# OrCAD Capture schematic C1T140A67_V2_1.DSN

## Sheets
1 002_Log: title: Telink-Semi; rev: V2.1; note: C1T140A67
2 001_chip: size A4
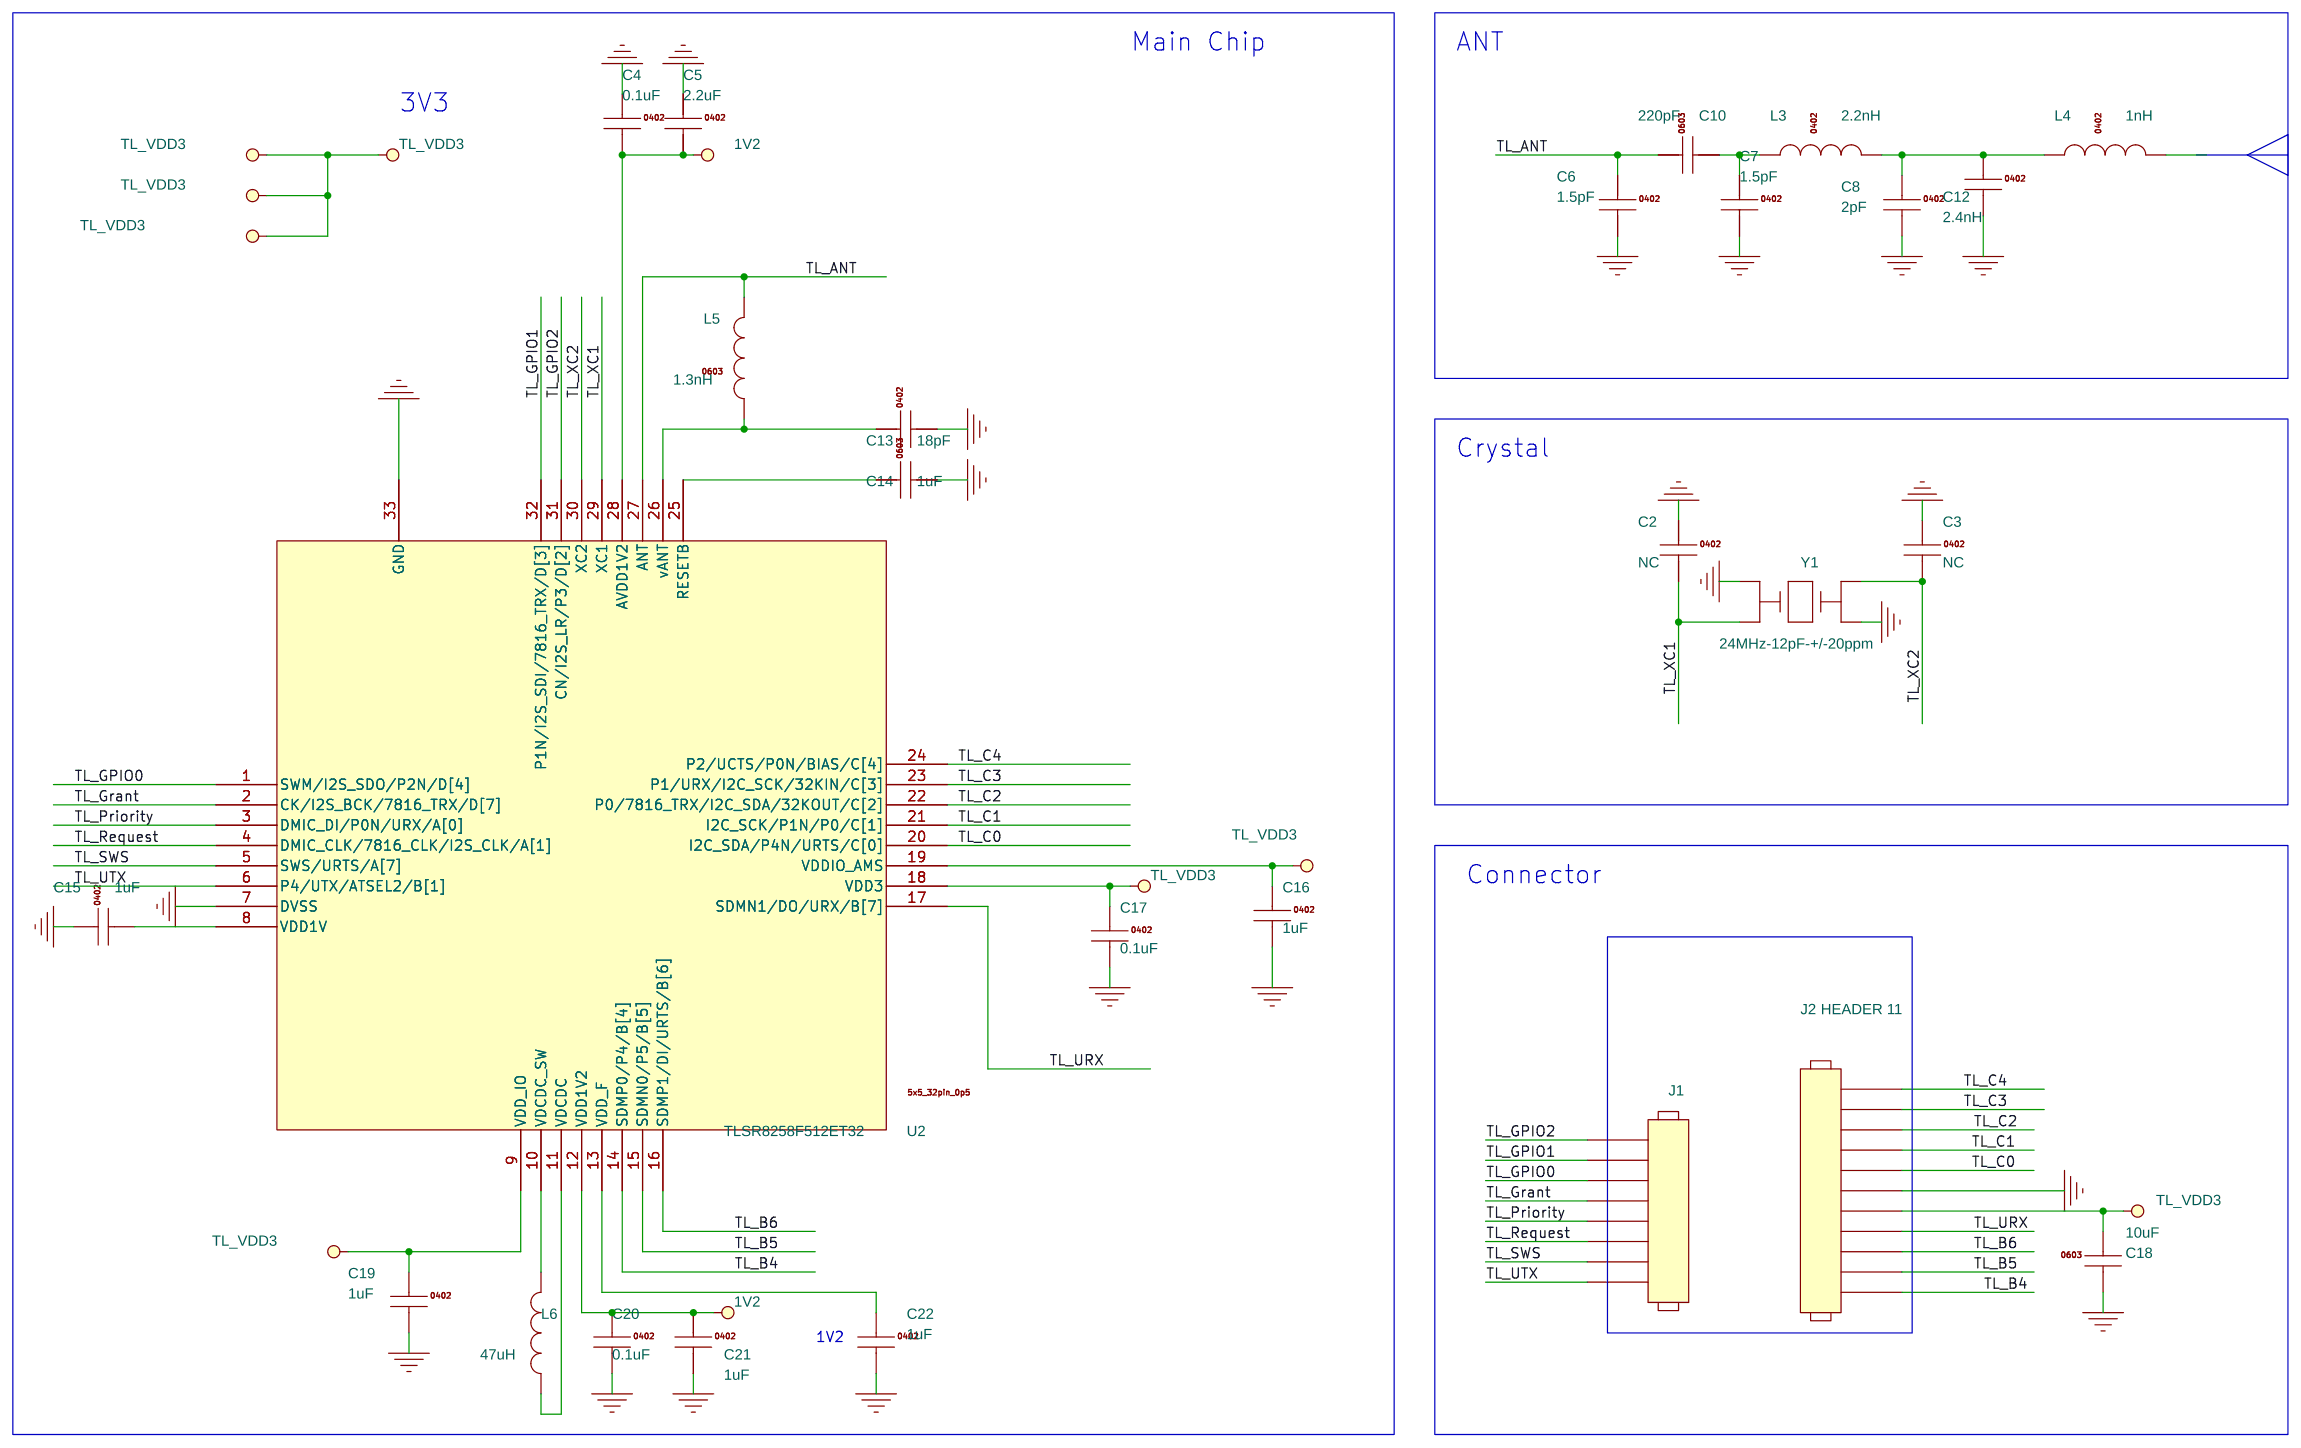
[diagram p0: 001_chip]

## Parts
C2  NC  [0201]
C3  NC  [0201]
C4  0.1uF  [0201]
C5  2.2uF  [0201]
C6  1.5pF  [0201]
C7  1.5pF  [0201]
C8  2pF  [0201]
C10  220pF  [0201]
C12  2.4nH  [0201]
C13  18pF  [0201]
C14  1uF  [0201]
C15  1uF  [0201]
C16  1uF  [0201]
C17  0.1uF  [0201]
C18  10uF  [0402]
C19  1uF  [0201]
C20  0.1uF  [0201]
C21  1uF  [0201]
C22  1uF  [0201]
J1  HEADER 8  [hdr_1p5_1x8]
J2  HEADER 11  [hdr_1p5_1x11]
L3  2.2nH  [0201]
L4  1nH  [0201]
L5  1.3nH  [0201]
L6  47uH  [0805L]
U2  TLSR8258F512ET32  [qfn_5x5_32pin_0p5_2p50x2p50]
Y1  24MHz-12pF-+/-20ppm  [osccc200x250x080]

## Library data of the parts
C2 C3 = C1005_NC
C4 C5 C16 C17 C19-C22 = C1005X5R1C104K
C6-C8 C12 = C1005C0G1H020C
C10 = C1608_NC
C13 = C1005C0G1H100D
C14 = C1608X5R1C105M
C15 = C1005X5R1C105K
C18 = C1608X5R0J106M
J1 = HEADER_8
J2 = HEADER_11
L3 L4 = MLK1005S3N3ST
L5 = MLK1608_000R
L6 = IND_0
U2 = TLSR8258F512ET32
Y1 = CRYSTAL4_SM_0

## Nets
1V2: C4.2 C5.2 C20.1 C21.1 U2.12(VDD1V2) U2.28(AVDD1V2)
GND: C2.1 C3.1 C4.1 C5.1 C6.2 C7.2 C8.2 C12.2 C13.2 C14.2 C15.1 C16.2 C17.2 C18.2 C19.2 C20.2 C21.2 C22.2 J2.6 U2.7(DVSS) U2.33(GND) Y1.2 Y1.4
TL_ANT: C6.1 C10.1 L5.2 U2.27(ANT)
TL_B4: J2.11 U2.14(SDMP0/P4/B[4])
TL_B5: J2.10 U2.15(SDMN0/P5/B[5])
TL_B6: J2.9 U2.16(SDMP1/DI/URTS/B[6])
TL_C0: J2.5 U2.20(I2C_SDA/P4N/URTS/C[0])
TL_C1: J2.4 U2.21(I2C_SCK/P1N/P0/C[1])
TL_C2: J2.3 U2.22(P0/7816_TRX/I2C_SDA/32KOUT/C[2])
TL_C3: J2.2 U2.23(P1/URX/I2C_SCK/32KIN/C[3])
TL_C4: J2.1 U2.24(P2/UCTS/P0N/BIAS/C[4])
TL_GPIO0: J1.3 U2.1(SWM/I2S_SDO/P2N/D[4])
TL_GPIO1: J1.2 U2.32(P1N/I2S_SDI/7816_TRX/D[3])
TL_GPIO2: J1.1 U2.31(CN/I2S_LR/P3/D[2])
TL_Grant: J1.4 U2.2(CK/I2S_BCK/7816_TRX/D[7])
TL_Priority: J1.5 U2.3(DMIC_DI/P0N/URX/A[0])
TL_Request: J1.6 U2.4(DMIC_CLK/7816_CLK/I2S_CLK/A[1])
TL_SWS: J1.7 U2.5(SWS/URTS/A[7])
TL_URX: J2.8 U2.17(SDMN1/DO/URX/B[7])
TL_UTX: J1.8 U2.6(P4/UTX/ATSEL2/B[1])
TL_VDD: C16.1 C17.1 C18.1 C19.1 J2.7 U2.9(VDD_IO) U2.18(VDD3) U2.19(VDDIO_AMS)
TL_XC1: C2.2 U2.29(XC1) Y1.3
TL_XC2: C3.2 U2.30(XC2) Y1.1
N19775240: C13.1 L5.1 U2.26(vANT)
N19775250: C14.1 U2.25(RESETB)
N19775943: C7.1 C10.2 L3.1
N19776303: C15.2 U2.8(VDD1V)
N19776990: L6.1 U2.11(VDCDC)
N19777000: L6.2 U2.10(VDCDC_SW)
N19777002: C22.1 U2.13(VDD_F)
N19779349: C8.1 C12.1 L3.2 L4.1

Not connected (* = marked no-connect by the designer): L4 2

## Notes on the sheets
sheet 2
- Main Chip
- ANT
- 3V3
- Crystal
- Connector
- 1V2
